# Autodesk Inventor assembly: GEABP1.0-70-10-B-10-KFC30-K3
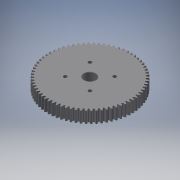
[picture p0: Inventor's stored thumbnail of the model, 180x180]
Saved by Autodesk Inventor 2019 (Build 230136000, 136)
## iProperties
Category: PARTsolutions
Company: MISUMI
Created: 2022-11
Part Number: GEABP1.0-70-10-B-10-KFC30-K3
Catalog Web Link: www.cadenas.de
Description: GEABM, GEABMS, GEABMT, GEABP, GEABPS, GEABPT, GEABA, GEABAS, GEABAT-Plastic Spur Gears - Pressure Angle 20 Degrees, Module 0.5/0.8/1.0/1.5/2.0/2.5/3.0
Vendor: MISUMI
Document SubType Name: Assembly
Designer: psAdmin
Manufacturer: MISUMI
Mass: 48.6002 g
Surface Area: 145.375 cm^2
Volume: 48.6002 cm^3
Density: 1 g/cm^3
Title: GEABP1.0-70-10-B-10-KFC30-K3
Author: Cadenas PARTsolutions
Comments: Plastic Spur Gears - Pressure Angle 20 Degrees, Module 0.5/0.8/1.0/1.5/2.0/2.5/3.0
PSOL_IDENT_0: {$CADENAS_DATA/23d-libs/misumi/metric/54_spur_gears/geabms20_asmtab.prj},415 {VTYP=3D},{STYP=ASSTAB}
PSOL_IDENT_1: ,{NB=GEABP1.0-70-10-B-10-KFC30-K3},{LINA=GEABP1.0-70-10-B-10-KFC30-K3},{NN=GEABM, GEABMS, GEABMT, GE
PSOL_IDENT_2: ABP, GEABPS, GEABPT, GEABA, GEABAS, GEABAT},{DATE=16.08.2021 10:08:31},{GEOMDATE=16.08.2021 10:08:28
PSOL_IDENT_3: },{VERSION=},{LINEID=30},{WBVAR=MATSG,MATCR,NT,B,TS,PS,ALT1,ALT2,TPC,ALT11,ALT10,BS,ALT3,Z,J,ALT4,Q,
PSOL_IDENT_4: R,S,T,ALT5,LFC,LTC,MALT5,ALT6,KFC,KTC,K},{WBNUMERIC=NT,B,BS,Z,J,Q,R,S,T,LFC,LTC,KFC,KTC,K}  {NB=GEAB
PSOL_IDENT_5: P1.0-70-10-B-10-KFC30-K3},{LINA=GEABP1.0-70-10-B-10-KFC30-K3},{KT=DUMMY},{PN=GEABP1.0-70-10-B-10-KFC
PSOL_IDENT_6: 30-K3},{TYPE=GEABP},{MATSG=PW},{MATSGALG='MCN','MC Nylon','PW','Polyacetal White','PB','Polyacetal B
PSOL_IDENT_7: lue'},{MATCR=},{MATCRALG='','-','S45C','1045 Carbon Steel','SUS304','304 Stainless Steel'},{MOD=1.0}
PSOL_IDENT_8: ,{MOD1=1.0},{NT=70},{NTALG=15,16,18,20,22,24,25,26,28,30,32,35,36,40,45,48,50,55,60,70,75,80,90,100,
PSOL_IDENT_9: 120},{B=10},{BALG=10,15},{TS=B},{TSALG='A','A','B','B'},{TSPN=-B},{PS=10},{PSALG='10','10','11','11'
PSOL_IDENT_10: ,'12','12','13','13','14','14','15','15','16','16','17','17','18','18','19','19','20','20','21','21'
PSOL_IDENT_11: ,'22','22','23','23','24','24','25','25','26','26','27','27','28','28'},{PSCRL='10','10','11','11','
PSOL_IDENT_12: 12','12','13','13','14','14','15','15','16','16','17','17','18','18','19','19','20','20','21','21','
PSOL_IDENT_13: 22','22','23','23','24','24','25','25','26','26','27','27','28','28'},{PSCRW='10','10','12','12','15'
PSOL_IDENT_14: ,'15','20','20'},{DD=70.0},{DD05=35},{DD08=56},{DD10=70},{DD15=105},{DD20=0},{DD25=0},{DD30=0},{D=72
PSOL_IDENT_15: .0},{D05=36},{D08=57.6},{D10=72},{D15=108},{D20=0},{D25=0},{D30=0},{G=67.50},{G05=33.75},{G08=54},{G
PSOL_IDENT_16: 10=67.5},{G15=101.25},{G20=0},{G25=0},{G30=0},{H=40.0},{L=20},{LL1=10},{LL2=4.0},{M=M4},{M3D=4},{P=1
PSOL_IDENT_17: 0.00},{DD1=0},{CIFR=15},{CIFM=4},{CIFK=0},{CIFTAP=1},{SCREW=4.000},{SCREWL=3.000},{ALT1=},{ALT1ALG=''
PSOL_IDENT_18: ,'w/o Set Screw','KC90','with KC90 (Set Screw)','KC120','with KC120 (Set Screw)'},{ALT1PN=},{ALT2=},
PSOL_IDENT_19: {ALT2ALG='','w/o TPC (Tapped Hole Dimension)','TPC','with TPC (Tapped Hole Dimension)'},{TPC=N/A},{T
PSOL_IDENT_20: PCALG='N/A'},{ALT2PN=},{KC=0},{ALT11=},{ALT11ALG='', 'w/o GBA (Gear bottom adjustment of phase focus
PSOL_IDENT_21: )', 'GBA', 'with GBA (Gear bottom adjustment of phase focus)' },{ALT11PN=},{DEG=0},{ALT10=},{ALT10AL
PSOL_IDENT_22: G= '','w/o BS (Boss Cut)','BS','with BS (Boss Cut)' },{ALT10PN=},{BS=0.0},{BSALG=0},{BSMIN=7.000},{B
PSOL_IDENT_23: SMINALG=7},{BSMAX=10},{LL13D=10},{LL23D=16},{ALT3=},{ALT3ALG= '','w/o Stepped Hole','DHL','with DHL
PSOL_IDENT_24: (Stepped Hole)','DHR','with DHR (Stepped Hole)' },{ALT3PN=},{ZJPN=},{ALT31=1},{ALT32=1},{Z=0},{ZALG=
PSOL_IDENT_25: 0},{ZMINL=12},{ZMAXL=63},{ZMINR=12},{ZMAXR=36},{ZPN=},{J=0.0},{JALG=0},{JMIN=2},{JMAX=0},{JPN=},{ALT
PSOL_IDENT_26: 4=},{ALT4ALG= '','w/o WDH (Both Ends Stepped Hole)','WDH','with WDH (Both Ends Stepped Hole)' },{ALT
PSOL_IDENT_27: 4PN=},{QRSTPN=},{LB=20.000},{Q=0},{QALG=0},{QMIN=12},{QMAX=36},{QPN=},{R=0},{RALG=0},{RMIN=12},{RMAX=
PSOL_IDENT_28: 36},{RPN=},{S=0},{SALG=0},{SMIN=3},{SMAX=14},{SPN=},{T=0},{TALG=0},{TMIN=3},{TMAX=0},{TPN=},{ALT5=},
PSOL_IDENT_29: {ALT5ALG= '','Not applicable' },{LFC=0},{LFCALG=0},{LTC=0},{LTCALG=0},{LPCDMIN=18},{LPCDMAX=60},{LCM
PSOL_IDENT_30: AX=63},{MALT5=N/A},{MALT5ALG= 'N/A' },{LCMAX2=60},{C=0.0},{ALT5PN=},{ALT6=KFC},{ALT6ALG= '','w/o Sid
PSOL_IDENT_31: e Through Hole','KFC','with KFC (Side Through Hole)','KTC','with KTC (Side Through Hole)' },{ALT6PN=
PSOL_IDENT_32: -KFC},{KFTCPN=30-K3},{KFC=30},{KFCALG=[17:33/1],[47:60/1]},{KFCPN=30},{KTC=0},{KTCALG=[0]},{KTCPN=},
PSOL_IDENT_33: {KPCDMIN1=17},{KPCDMAX1=33},{KPCDMIN2=47},{KPCDMAX2=60},{K=3.0},{KALG=[3:6/0.5]},{KPCD=30},{KPN=-K3}
PSOL_IDENT_34: ,{AG=0},{LBS=20},{PCD=30},{SHN=4},{SHDEG1=45},{SHDEG2=90},{PZQRDD2=10},{PPATH=geabms20/geabms20_asmt
PSOL_IDENT_35: pl.prj}
NB: GEABP1.0-70-10-B-10-KFC30-K3
NN: GEABM, GEABMS, GEABMT, GEABP, GEABPS, GEABPT, GEABA, GEABAS, GEABAT
NT: 70
NBSYN: $PN.
LINA: GEABP1.0-70-10-B-10-KFC30-K3
CATALOG: Misumi
PN: GEABP1.0-70-10-B-10-KFC30-K3
MATSG: Polyacetal White
MATCR: -
MOD: 1.0
B: 10
TS: B
PS: 10
DD: 70
D: 72
G: 67.5
H: 40
L: 20
LL1: 10
LL2: 4
M: M4
DD1: 0
ALT1: w/o Set Screw
ALT2: w/o TPC (Tapped Hole Dimension)
TPC: N/A
ALT11: w/o GBA (Gear bottom adjustment of phase focus)
ALT10: w/o BS (Boss Cut)
BS: 0
ALT3: w/o Stepped Hole
Z: 0
J: 0
ALT4: w/o WDH (Both Ends Stepped Hole)
Q: 0
R: 0
S: 0
T: 0
ALT5: Not applicable
LFC: 0
LTC: 0
MALT5: N/A
C: 0
ALT6: with KFC (Side Through Hole)
KFC: 30
KTC: 0
K: 3
SUPPLIER: MISUMI
ARTICLENO: GEABP1.0-70-10-B-10-KFC30-K3
BOMINFO: GEABP1.0-70-10-B-10-KFC30-K3
CREATOR: CADENAS GmbH
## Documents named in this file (3)
- e:\temp\worker_COMMON_6\temp\tmp_7836_18_Onr0q\format_0\GEABP1_0-70-10-B-10-KFC30-K3.iam
- e:\temp\worker_COMMON_6\temp\tmp_7836_18_Onr0q\format_0\GEABP1_0-70-10-B-10-KFC30-K3_b.ipt
- e:\temp\worker_COMMON_6\temp\tmp_7836_18_Onr0q\format_0\SET-SCREW4-3.ipt
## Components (2 placed, 2 different names)
1. GEABP1_0-70-10-B-10-KFC30-K3_b:1 — gear_to_screw_XY@1 <-> CP_XY@2, gear_to_screw_Z@1 <-> CP_Z@2, gear_to_screw_YZ@1 <-> CP_YZ@2
2. SET-SCREW4-3:1 — gear_to_screw_XY@1 <-> CP_XY@2, gear_to_screw_Z@1 <-> CP_Z@2, gear_to_screw_YZ@1 <-> CP_YZ@2
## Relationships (3: Mate 2, Angle 1)
- gear_to_screw_XY@1 <-> CP_XY@2 [Mate]: GEABP1_0-70-10-B-10-KFC30-K3_b:1 ↔ SET-SCREW4-3:1
- gear_to_screw_Z@1 <-> CP_Z@2 [Mate]: GEABP1_0-70-10-B-10-KFC30-K3_b:1 ↔ SET-SCREW4-3:1
- gear_to_screw_YZ@1 <-> CP_YZ@2 [Angle]: GEABP1_0-70-10-B-10-KFC30-K3_b:1 ↔ SET-SCREW4-3:1
